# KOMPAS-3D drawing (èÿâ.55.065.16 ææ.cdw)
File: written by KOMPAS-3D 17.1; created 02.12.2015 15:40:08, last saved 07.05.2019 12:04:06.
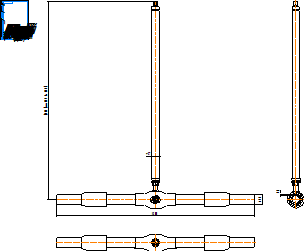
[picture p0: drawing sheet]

Sheet 1: A4, portrait

Title block, sheet 1: name: КШГ.55.065.16 СС; material: Внимание! Данный продукт является объектом авторского права ООО «Торговый Дом АДЛ». / Запрещается изменение, копирование, распространение / (в том числе путем копирования на другие сайты и ресурсы в Интернете) / или любое иное использование информации и объектов без предварительного / согласия правообладателя (ООО «Торговый Дом АДЛ»).; sheets: 1; organisation: ООО "Торговый дом АДЛ"; sheet format: A4; stored path: C:\Users\kka\KOMPAS_Work\Модели кранов для исследований\DN50\С удлинением\КШГ.32.050.40 СС ГЧ _ Шаровой кран БИВАЛ Ду50 Ру4 МПа редуцированный под приварку, с удлинением штока H=1100.cdw; drawn by: Климкович К.А.; drawn by, date: 02.12.15

Views: Вид 1, Проекционный вид 2, Проекционный вид 3
Referenced files in C:\Users\kka\KOMPAS_Work\Модели кранов для исследований\DN80\С удлинением\: КШТ.22.080.25 СС.a3d, КШГ.35.065.25 СС.a3d!КШГ.45.065.10 СС!Деталь (локальная).m3d
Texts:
  Klimkovich
  ADL
  (от 297 до 5000)
Dimensions and other numbers on the sheet: 1500; 75; 57; 8,4; 1:1; 1; 02.12.15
